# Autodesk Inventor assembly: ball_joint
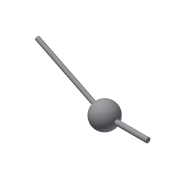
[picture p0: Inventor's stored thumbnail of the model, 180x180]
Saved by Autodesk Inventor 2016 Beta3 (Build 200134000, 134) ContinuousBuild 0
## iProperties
Created: 2016-03
Part Number: ball_joint
Document SubType Name: Assembly
Designer: Gaurav
Author: Gaurav
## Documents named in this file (3)
- D:\My Data\Books_Final Books\Autodesk Inventor 2015_resources\Chapter 7\Ball_Joint\ball_joint.iam
- D:\My Data\Books_Final Books\Autodesk Inventor 2015_resources\Chapter 7\Ball_Joint\Base.ipt
- D:\My Data\Books_Final Books\Autodesk Inventor 2015_resources\Chapter 7\Ball_Joint\movable_shaft.ipt
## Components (2 placed, 2 different names)
1. Base:1 — Mate:1, Mate:2, Ball:1
2. movable_shaft:1 — Ball:1
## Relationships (3: Mate 2, BallJoint 1)
- Mate:1: Base:1
- Mate:2: Base:1
- Ball:1: Base:1 ↔ movable_shaft:1
